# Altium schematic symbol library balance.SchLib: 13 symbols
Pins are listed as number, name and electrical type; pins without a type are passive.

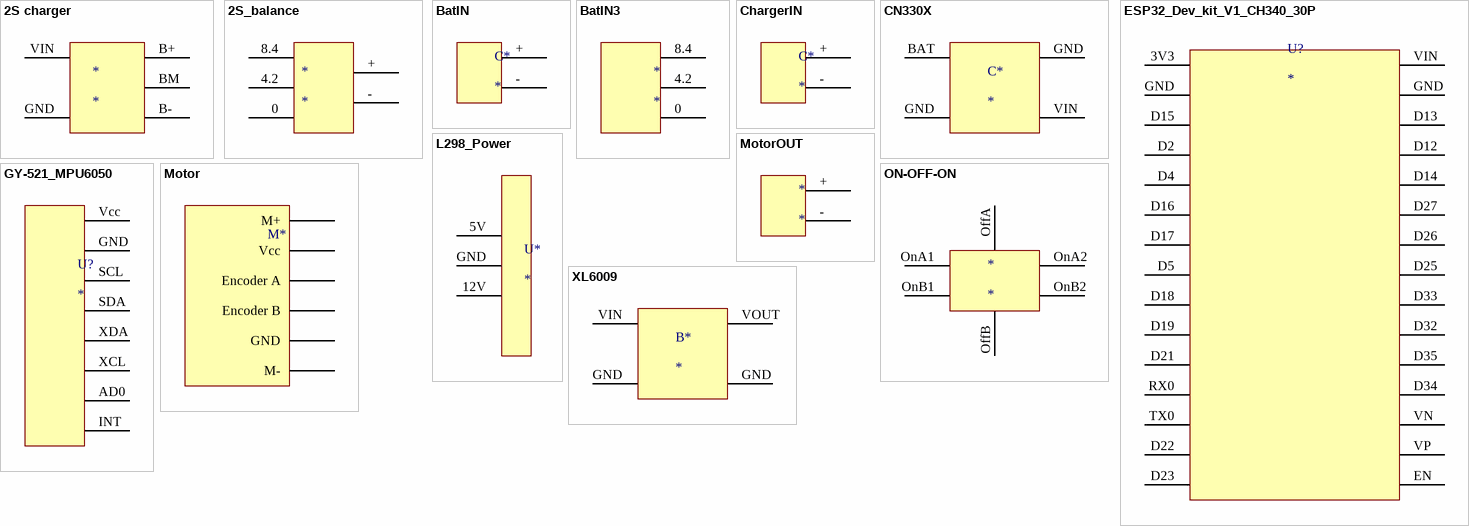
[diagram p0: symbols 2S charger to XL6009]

## 2S charger
designator *
footprint 2S_charge
pins: B+, B-, BM, GND, VIN

## 2S_balance
designator *
footprint 2S_balance
pins: 0, 4.2, 8.4, +, -

## BatIN
designator C*
footprint BatIN
pins: +, -

## BatIN3
designator *
footprint BatIN3
pins: 0, 4.2, 8.4

## ChargerIN
designator C*
footprint ChargerIN
pins: +, -

## CN330X
designator C*
footprint CN330X
pins: BAT, GND, GND, VIN

## ESP32_Dev_kit_V1_CH340_30P
designator U?
footprint ESP32
pins: 3V3, D2, D4, D5, D12, D13, D14, D15, D16, D17, D18, D19, D21, D22, D23, D25, D26, D27, D32, D33, D34, D35, EN, GND, GND, RX0, TX0, VIN, VN, VP

## GY-521_MPU6050
designator U?
footprint GY-521_MPU6050
pins: AD0, GND, INT, SCL, SDA, Vcc, XCL, XDA

## L298_Power
designator U*
footprint L298N_POWER
pins: 5V, 12V, GND

## Motor
designator M*
Motor with encoder
footprint Motor
pins: Encoder A, Encoder B, GND, M+, M-, Vcc

## MotorOUT
designator *
footprint MotorOUT
pins: +, -

## ON-OFF-ON
designator *
footprint ON-OFF-ON
pins: OffA, OffB, OnA1, OnA2, OnB1, OnB2

## XL6009
designator B*
footprint XL6009
pins: GND, GND, VIN, VOUT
